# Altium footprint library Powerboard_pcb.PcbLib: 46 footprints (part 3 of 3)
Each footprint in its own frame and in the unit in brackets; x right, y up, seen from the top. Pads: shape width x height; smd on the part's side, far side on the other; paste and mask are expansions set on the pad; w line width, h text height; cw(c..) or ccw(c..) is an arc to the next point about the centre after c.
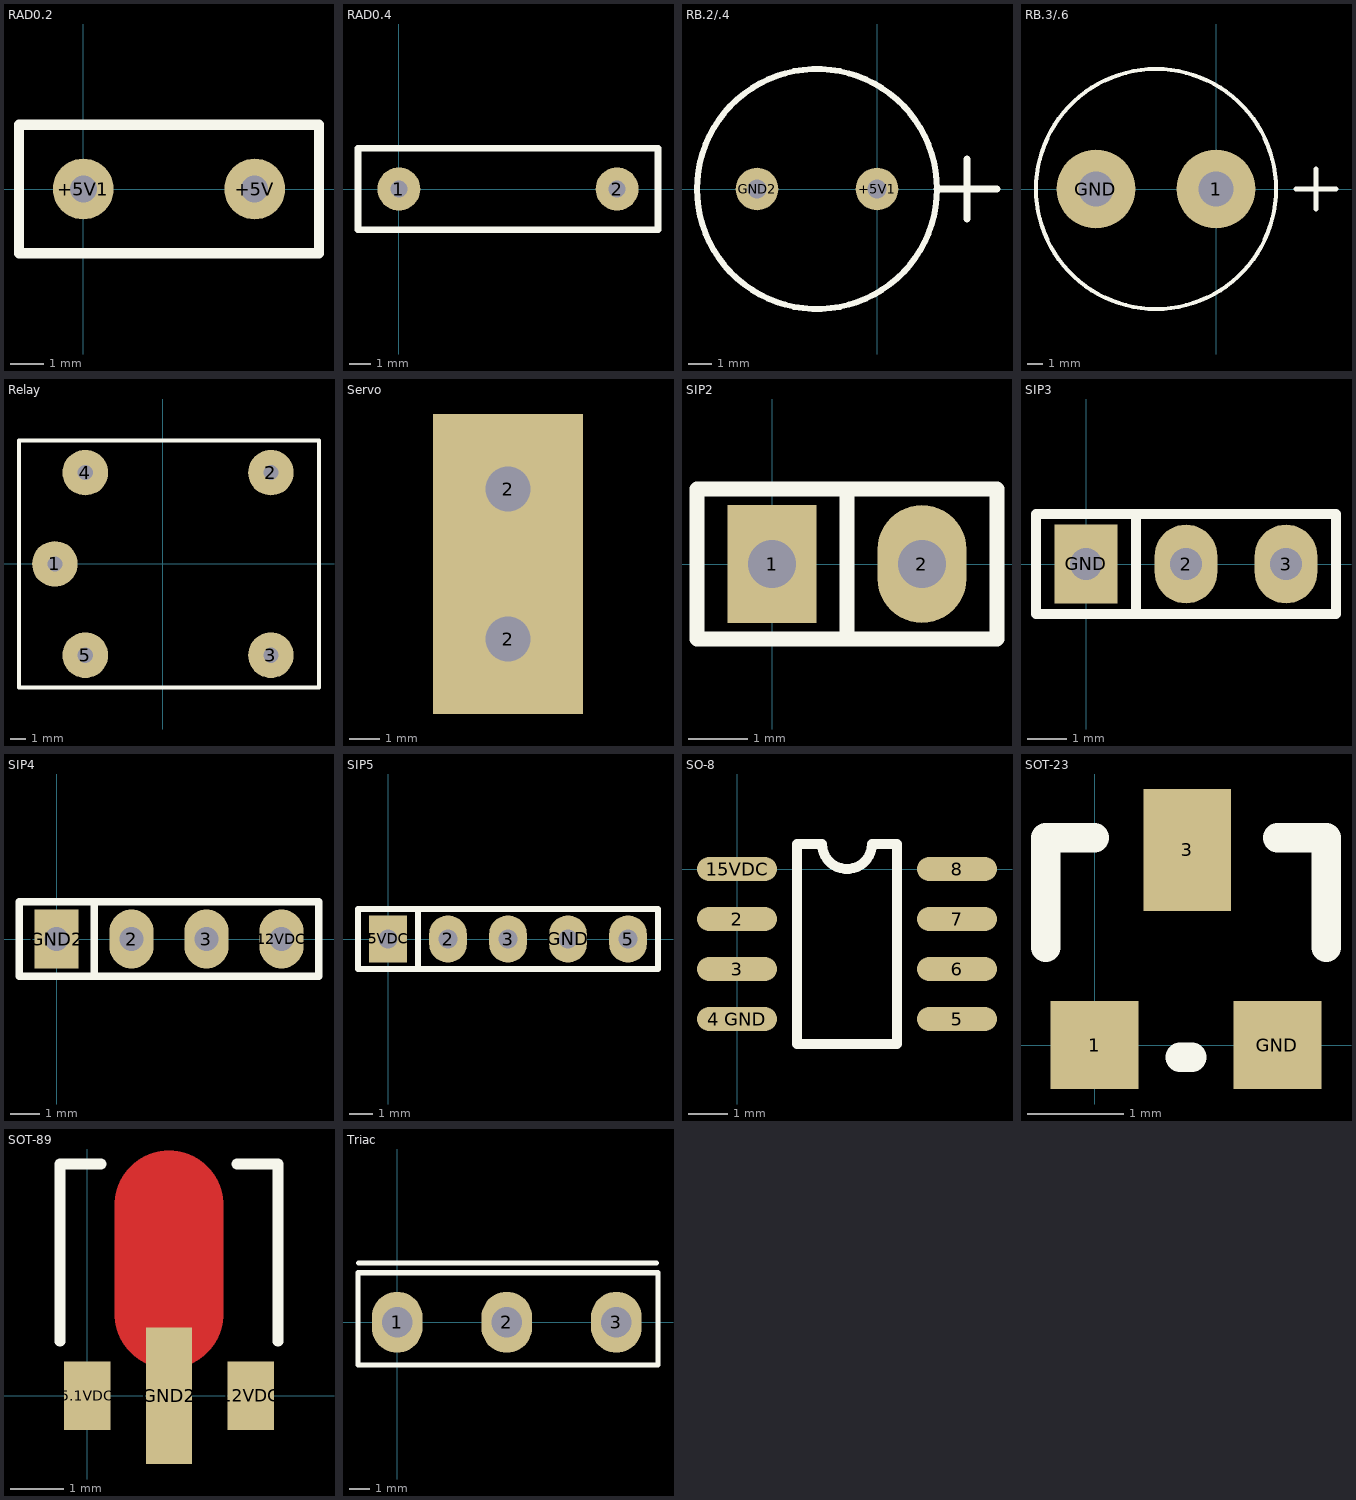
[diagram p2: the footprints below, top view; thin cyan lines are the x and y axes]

## RAD0.2 [mm]
pads (2):
  round 1.8 hole 0.8: +5V(5.08,0) +5V1(0,0)
Top Overlay:
  lines w0.305: -1.905,-1.905 -1.905,1.905 6.985,1.905 6.985,-1.905 -1.905,-1.905

## RAD0.4 [mm]
pads (2):
  round 2 hole 0.8: 1(0,0) 2(10.16,0)
Top Overlay:
  lines w0.305: -1.905,-1.905 -1.905,1.905 12.065,1.905 12.065,-1.905 -1.905,-1.905

## RB.2/.4 [mm]
pads (2):
  round 1.8 hole 0.8: +5V1(0,0) GND2(-5.08,0)
Top Overlay:
  circle w0.254: c-2.54,0 r5.08
  lines w0.305: 2.54,0 5.08,0 ; 3.81,-1.27 3.81,1.27

## RB.3/.6 [mm]
pads (2):
  round 5 hole 2.2: 1(0,0) GND(-7.62,0)
Top Overlay:
  circle w0.254: c-3.81,0 r7.62
  lines w0.305: 5.08,0 7.62,0 ; 6.35,-1.27 6.35,1.27

## Relay [mm]
pads (5):
  round 3 hole 1: 1(-7.1,0) 2(7.1,6) 3(7.1,-6) 4(-5.1,6) 5(-5.1,-6)
Top Overlay:
  lines w0.254: -9.459,-8.135 -9.459,8.121 10.261,8.121 10.261,-8.135 -9.459,-8.135

## Servo [mm]
pads (2):
  rect 5x5 hole 1.5: 2(-271.792,-287.933) 2(-271.792,-282.933)

## SIP2 [mm]
pads (2):
  rect 1.5x2 hole 0.813: 1(0,0)
  oval 1.5x2 hole 0.813: 2(2.54,0)
Top Overlay:
  lines w0.254: 1.27,-1.27 1.27,1.27 ; -1.27,-1.27 -1.27,1.27 3.81,1.27 3.81,-1.27 -1.27,-1.27

## SIP3 [mm]
pads (3):
  oval 1.6x2 hole 0.813: 2(2.54,0) 3(5.08,0)
  rect 1.6x2 hole 0.813: GND(0,0)
Top Overlay:
  lines w0.254: 1.27,-1.27 1.27,1.27 ; -1.27,-1.27 -1.27,1.27 6.35,1.27 6.35,-1.27 -1.27,-1.27

## SIP4 [mm]
pads (4):
  oval 1.5x2 hole 0.813: 2(2.54,0) 3(5.08,0) 12VDC(7.62,0)
  rect 1.5x2 hole 0.813: GND2(0,0)
Top Overlay:
  lines w0.254: 1.27,-1.27 1.27,1.27 ; -1.27,-1.27 8.89,-1.27 8.89,1.27 -1.27,1.27 -1.27,-1.27

## SIP5 [mm]
pads (5):
  oval 1.6x2 hole 0.813: 2(2.54,0) 3(5.08,0) 5(10.16,0) GND(7.62,0)
  rect 1.6x2 hole 0.813: 5VDC(0,0)
Top Overlay:
  lines w0.254: 1.27,-1.27 1.27,1.27 ; -1.27,-1.27 -1.27,1.27 11.43,1.27 11.43,-1.27 -1.27,-1.27

## SO-8 [mil]
pads (8):
  oval 80x24 smd: 2(0,-50) 3(0,-100) "4 GND"(0,-150) 5(220,-150) 6(220,-100) 7(220,-50) 8(220,0) 15VDC(0,0)
Top Overlay:
  lines w10: 60,-175 160,-175 160,25 135,25 cw(c110,25) 85,25 60,25 60,-175

## SOT-23 [mil]
pads (3):
  rect 36x36 smd: 1(0,0) GND(75,0)
  rect 36x50 smd: 3(38,80)
Top Overlay:
  lines w12: -20,40 -20,85 0,85 ; 35,-5 40,-5 ; 75,85 95,85 95,40

## SOT-89 [mil]
pads (3):
  rect 34x50 smd: 5.1VDC(0,0) 12VDC(120,0)
  rect 34x100 smd: GND2(60,0)
Top Layer:
  lines w80: 60,60 60,140
Top Overlay:
  lines w8: -20,40 -20,170 10,170 ; 110,170 140,170 140,40

## Triac [mm]
pads (3):
  oval 2.5x3 hole 1.5: 1(0,0) 2(5.4,0) 3(10.8,0)
Top Overlay:
  lines w0.254: -1.905,2.921 12.777,2.921 ; 12.852,-2.108 12.852,2.439 ; 12.853,-2.108 -1.93,-2.108 -1.93,2.438 12.853,2.438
